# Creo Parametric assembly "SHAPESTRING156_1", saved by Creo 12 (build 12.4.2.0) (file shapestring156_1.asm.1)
Units: Custom; MM, KILOGRAM, SECS

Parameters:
  PTC_WM_ITERATION = "0"
  PTC_WM_VERSION = "-.0"
  PTC_WM_LIFECYCLE_STATE = "In Work"
  PTC_WM_LIFECYCLE = "MO_CADDocument"
  PTC_WM_CREATED_BY = "Maximilian Roepper (Z0017RMS: MO)"
  PTC_WM_CREATED_ON = "18-Sep-26 11:36:42 AM"
  PTC_WM_MODIFIED_BY = "Maximilian Roepper (Z0017RMS: MO)"
  PTC_WM_MODIFIED_ON = "18-Sep-26 11:36:46 AM"
  PDMLINKNUMBER = "PDM000071454921"
  PTC_WM_NUMBER = "PDM000071454921"

Other parameters: WEIGHT, WEIGHT_FACTOR, WEIGHT_ADD, MC_ERRORS, SUPPLIER

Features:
  1. coordinate system
  2. imported feature
  3. component "SHAPESTRING076_1"
  4. component "SHAPESTRING148_1"
  5. component "SHAPESTRING149_1"
  6. component "SHAPESTRING150_1"
  7. component "SHAPESTRING151_1"
  8. component "SHAPESTRING152_1"
  9. component "SHAPESTRING153_1"
  10. component "SHAPESTRING154_1"
  11. component "SHAPESTRING155_1"

Other named items: DRW_VIEW_ORG, ROUGH-GROB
